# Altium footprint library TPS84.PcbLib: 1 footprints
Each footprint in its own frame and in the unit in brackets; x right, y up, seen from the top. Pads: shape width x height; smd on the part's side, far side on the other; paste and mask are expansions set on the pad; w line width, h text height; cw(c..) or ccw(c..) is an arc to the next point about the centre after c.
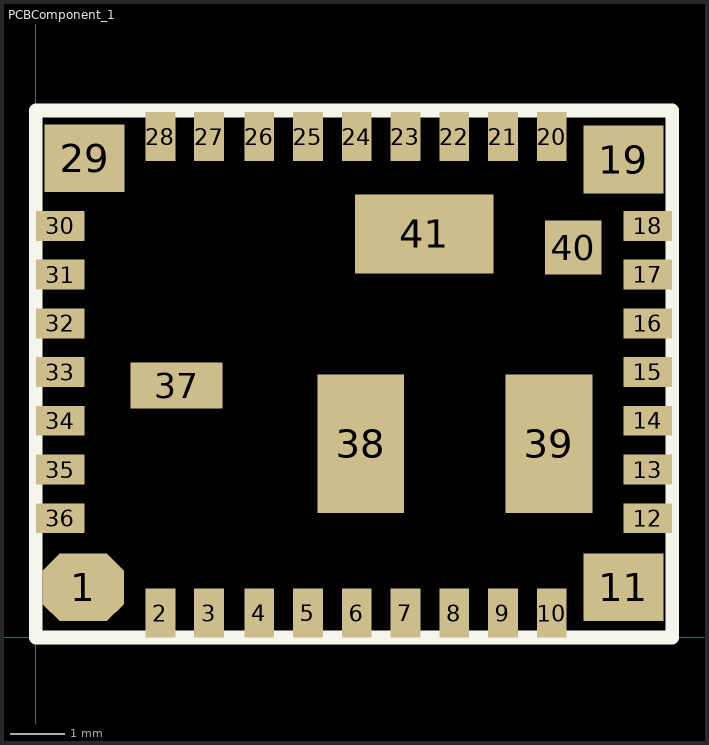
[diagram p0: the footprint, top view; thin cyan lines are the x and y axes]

## PCBComponent_1 [mm]
pads (41):
  oct 1.5x1.25 smd: 1(0.875,0.925)
  rect 0.55x0.9 smd: 2(2.3,0.45) 3(3.2,0.45) 4(4.125,0.45) 5(5.025,0.45) 6(5.925,0.45) 7(6.825,0.45) 8(7.725,0.45) 9(8.625,0.45) 10(9.525,0.45) 20(9.525,9.25) 21(8.625,9.25) 22(7.725,9.25) 23(6.825,9.25) 24(5.925,9.25) 25(5.025,9.25) 26(4.125,9.25) 27(3.2,9.25) 28(2.3,9.25)
  rect 1.475x1.25 smd: 11(10.85,0.925) 19(10.85,8.825) 29(0.9,8.85)
  rect 0.9x0.55 smd: 12(11.3,2.2) 13(11.3,3.1) 14(11.3,4) 15(11.3,4.9) 16(11.3,5.8) 17(11.3,6.7) 18(11.3,7.6) 30(0.45,7.6) 31(0.45,6.7) 32(0.45,5.8) 33(0.45,4.9) 34(0.45,4) 35(0.45,3.1) 36(0.45,2.2)
  rect 1.7x0.85 smd: 37(2.6,4.65)
  rect 1.6x2.56 smd: 38(6,3.575) 39(9.475,3.575)
  rect 1.04x1 smd: 40(9.925,7.2)
  rect 2.56x1.46 smd: 41(7.175,7.45)
Top Overlay:
  lines w0.254: 0,0 11.75,0 11.75,9.73 0,9.73 0,0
